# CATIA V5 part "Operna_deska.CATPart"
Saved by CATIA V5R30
Part number: Operna_deska
Definition: F 60_346446_36_1730
Nomenclature: F 60_346446_36_1730
Source: Unknown
Description: PART--DESC
Bounding box of the stored display mesh (mm): x -223 to 223, y -173 to 173, z -128 to -92
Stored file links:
  E:\Bakalarka\Model\Forma_v7\Operna_deska.CATPart
  E:\Bakalarka\Model\Forma_v7\Vyhazovaci_cast.CATProduct
  E:\Bakalarka\Model\Sestava_formy_1\Forma_Vyhazovaci_cast.CATPart
  E:\Bakalarka\Model\Chyba catie 2\Forma_Vyhazovaci_cast.CATPart
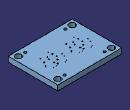
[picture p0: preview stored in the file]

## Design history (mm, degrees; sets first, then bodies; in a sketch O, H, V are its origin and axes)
Body1 "MANIFOLD_SOLID_BREP #4115" (main body)
  Solid1: solid without history
  Body2 "Result of __DrillHole"
    Solid2: linked copy from another document
  Assemble1 "DrillHoleEjector_E1710_7.1": tool Body2
  Body3 "Result of __DrillHole"
    Solid3: linked copy from another document
  Assemble2 "DrillHoleEjector_E1710_8.1": tool Body3
  Body4 "Result of __DrillHole"
    Solid4: linked copy from another document
  Assemble3 "DrillHoleEjector_E1710_9.1": tool Body4
  Body5 "Result of __DrillHole"
    Solid5: linked copy from another document
  Assemble4 "DrillHoleEjector_E1710_10.1": tool Body5
  Body6 "Result of __DrillHole"
    Solid6: linked copy from another document
  Assemble5 "DrillHoleEjector_E1710_11.1": tool Body6
  Body7 "Result of __DrillHole"
    Solid7: linked copy from another document
  Assemble6 "DrillHoleEjector_E1710_31.1": tool Body7
  Body8 "Result of __DrillHole"
    Solid8: linked copy from another document
  Assemble7 "DrillHoleEjector_E1710_32.1": tool Body8
  Body9 "Result of __DrillHole"
    Solid9: linked copy from another document
  Assemble8 "DrillHoleEjector_E1710_33.1": tool Body9
  Body10 "Result of __DrillHole"
    Solid10: linked copy from another document
  Assemble9 "DrillHoleEjector_E1710_34.1": tool Body10
  Body11 "Result of __DrillHole"
    Solid11: linked copy from another document
  Assemble10 "DrillHoleEjector_E1710_35.1": tool Body11
  Body12 "Result of __DrillHole"
    Solid12: linked copy from another document
  Assemble11 "DrillHoleEjector_E1710_36.1": tool Body12
  Body13 "Result of __DrillHole"
    Solid13: linked copy from another document
  Assemble12 "DrillHoleEjector_E1710_37.1": tool Body13
  DatumCurve1 to DatumCurve7
  DatumSurface1
  DatumSurface2
  DatumCurve8 to DatumCurve41
  Sketch1 on face of DatumSurface1, origin (0, 0, -198), H (1, 0, 0), V (0, 1, 0)
    projected circle E1 centre (55, -53) radius 2.3 from edge of DatumCurve8
    projected circle E2 centre (60, -57.5) radius 1.55 from edge of DatumCurve9
    projected circle E3 centre (125.5, -45) radius 4 from edge of DatumCurve10
    projected circle E4 centre (135, -10) radius 4 from edge of DatumCurve11
    projected circle E5 centre (54.5, -4) radius 4 from edge of DatumCurve12
    projected circle E6 centre (20.5, 0) radius 2.3 from edge of DatumCurve13
    projected circle E7 centre (25.5, 22.5) radius 2.3 from edge of DatumCurve14
    projected circle E8 centre (72, 20) radius 4 from edge of DatumCurve15
    projected circle E9 centre (100, 25) radius 4 from edge of DatumCurve16
    projected circle E10 centre (156, 21.5) radius 2.3 from edge of DatumCurve17
    projected circle E11 centre (150, 15) radius 1.55 from edge of DatumCurve18
    projected circle E12 centre (95, 44.5) radius 4 from edge of DatumCurve19
    projected circle E13 centre (113.5, 54.5) radius 2.3 from edge of DatumCurve20
    projected circle E14 centre (133, 53.5) radius 1.55 from edge of DatumCurve21
    projected circle E15 centre (58, 61) radius 1.55 from edge of DatumCurve22
    projected circle E16 centre (44.5, 54.5) radius 1.55 from edge of DatumCurve23
    projected circle E17 centre (54.5, -33) radius 4 from edge of DatumCurve24
    projected circle E18 centre (-54.5, -45) radius 4 from edge of DatumCurve25
    projected circle E19 centre (-120, -57.5) radius 1.55 from edge of DatumCurve26
    projected circle E20 centre (-125, -53) radius 2.3 from edge of DatumCurve27
    projected circle E21 centre (-125.5, -33) radius 4 from edge of DatumCurve28
    projected circle E22 centre (-125.5, -4) radius 4 from edge of DatumCurve29
    projected circle E23 centre (-159.5, 0) radius 2.3 from edge of DatumCurve30
    projected circle E24 centre (-154.5, 22.5) radius 2.3 from edge of DatumCurve31
    projected circle E25 centre (-108, 20) radius 4 from edge of DatumCurve32
    projected circle E26 centre (-80, 25) radius 4 from edge of DatumCurve33
    projected circle E27 centre (-85, 44.5) radius 4 from edge of DatumCurve34
    projected circle E28 centre (-66.5, 54.5) radius 2.3 from edge of DatumCurve35
    projected circle E29 centre (-47, 53.5) radius 1.55 from edge of DatumCurve36
    projected circle E30 centre (-122, 61) radius 1.55 from edge of DatumCurve37
    projected circle E31 centre (-135.5, 54.5) radius 1.55 from edge of DatumCurve38
    projected circle E32 centre (-45, -10) radius 4 from edge of DatumCurve39
    projected circle E33 centre (-30, 15) radius 1.55 from edge of DatumCurve40
    projected circle E34 centre (-24, 21.5) radius 2.3 from edge of DatumCurve41
  Sketch2 on face of Solid1, origin (0, 0, -92), H (1, 0, 0), V (0, 1, 0)
    projected circle E1 centre (55, -53) radius 2.3 from Sketch1
    projected circle E2 centre (60, -57.5) radius 1.55 from Sketch1
    projected circle E3 centre (125.5, -45) radius 4 from Sketch1
    projected circle E4 centre (135, -10) radius 4 from Sketch1
    projected circle E5 centre (54.5, -4) radius 4 from Sketch1
    projected circle E6 centre (20.5, 0) radius 2.3 from Sketch1
    projected circle E7 centre (25.5, 22.5) radius 2.3 from Sketch1
    projected circle E8 centre (72, 20) radius 4 from Sketch1
    projected circle E9 centre (100, 25) radius 4 from Sketch1
    projected circle E10 centre (156, 21.5) radius 2.3 from Sketch1
    projected circle E11 centre (150, 15) radius 1.55 from Sketch1
    projected circle E12 centre (95, 44.5) radius 4 from Sketch1
    projected circle E13 centre (113.5, 54.5) radius 2.3 from Sketch1
    projected circle E14 centre (133, 53.5) radius 1.55 from Sketch1
    projected circle E15 centre (58, 61) radius 1.55 from Sketch1
    projected circle E16 centre (44.5, 54.5) radius 1.55 from Sketch1
    projected circle E17 centre (54.5, -33) radius 4 from Sketch1
    projected circle E18 centre (-54.5, -45) radius 4 from Sketch1
    projected circle E19 centre (-120, -57.5) radius 1.55 from Sketch1
    projected circle E20 centre (-125, -53) radius 2.3 from Sketch1
    projected circle E21 centre (-125.5, -33) radius 4 from Sketch1
    projected circle E22 centre (-125.5, -4) radius 4 from Sketch1
    projected circle E23 centre (-159.5, 0) radius 2.3 from Sketch1
    projected circle E24 centre (-154.5, 22.5) radius 2.3 from Sketch1
    projected circle E25 centre (-108, 20) radius 4 from Sketch1
    projected circle E26 centre (-80, 25) radius 4 from Sketch1
    projected circle E27 centre (-85, 44.5) radius 4 from Sketch1
    projected circle E28 centre (-66.5, 54.5) radius 2.3 from Sketch1
    projected circle E29 centre (-47, 53.5) radius 1.55 from Sketch1
    projected circle E30 centre (-122, 61) radius 1.55 from Sketch1
    projected circle E31 centre (-135.5, 54.5) radius 1.55 from Sketch1
    projected circle E32 centre (-45, -10) radius 4 from Sketch1
    projected circle E33 centre (-30, 15) radius 1.55 from Sketch1
    projected circle E34 centre (-24, 21.5) radius 2.3 from Sketch1
  Pocket1: profile Sketch2, direction (0, 0, -1), length 36
  DatumCurve42
  DatumCurve43
  Body14 "Result of __DrillHole"
    Solid14: linked copy from another document
  Assemble13 "DrillHoleEjector_E1710_1.2": tool Body14
  Body15 "Result of __DrillHole"
    Solid15: linked copy from another document
  Assemble14 "DrillHoleEjector_E1710_2.2": tool Body15
  Body16 "Result of __DrillHole"
    Solid16: linked copy from another document
  Assemble15 "DrillHoleEjector_E1710_3.2": tool Body16
  Body17 "Result of __DrillHole"
    Solid17: linked copy from another document
  Assemble16 "DrillHoleEjector_E1710_4.2": tool Body17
